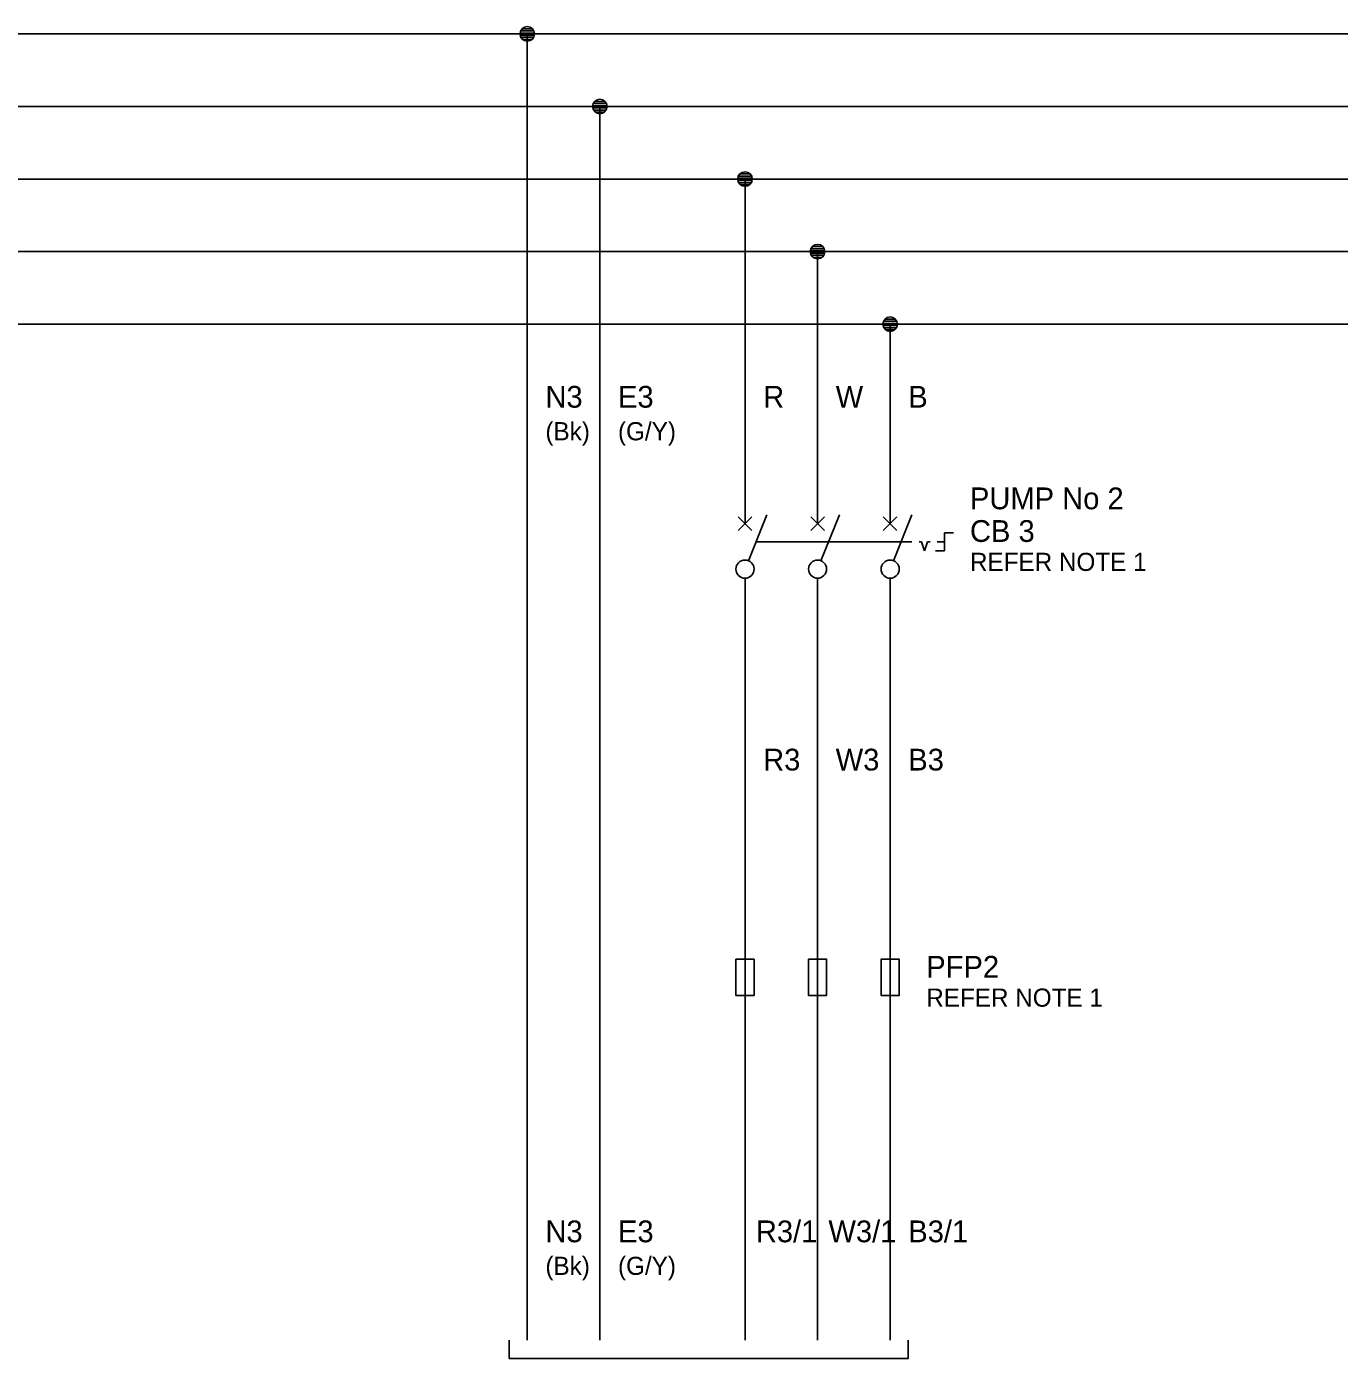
# Model space of a CAD drawing. Extents: x 0 to 841, y 0 to 594.
# Drawn here: x 491 to 671.9, y 147.5 to 331 of the extents above; entities that cross this region are included whole.
import ezdxf

# ---------------------------------------------------------------- set-up
doc = ezdxf.new("R2010")
doc.units = 0
doc.layers.add('Level 1', color=7, linetype='Continuous')
doc.layers.add('Level 10', color=7, linetype='Continuous')

msp = doc.modelspace()

# ---------------------------------------------------------------- linework, layer by layer
at = {"layer": 'Level 1'}
for p, q in [((50, 330), (800, 330)), ((560, 330), (560, 150)), ((50, 320), (800, 320)), ((570, 320), (570, 150)), ((800, 310), (50, 310)), ((590, 310), (590, 265)), ((50, 300), (800, 300)), ((600, 300), (600, 265)), ((50, 290), (800, 290)), ((610, 290), (610, 265)), ((590, 262.5), (590, 265)), ((600, 262.5), (600, 265)), ((610, 262.5), (610, 265)), ((589.06, 263.44), (590.94, 261.56)), ((590.94, 263.44), (589.06, 261.56)), ((590.46, 257.41), (593, 263.75)), ((599.06, 263.44), (600.94, 261.56)), ((600.94, 263.44), (599.06, 261.56)), ((600.46, 257.41), (603, 263.75)), ((609.06, 263.44), (610.94, 261.56)), ((610.94, 263.44), (609.06, 261.56)), ((610.46, 257.41), (613, 263.75)), ((591.5, 260), (611.5, 260)), ((590, 255), (590, 150)), ((600, 255), (600, 150)), ((610, 255), (610, 150))]:
    msp.add_line(p, q, dxfattribs=at)
msp.add_lwpolyline([(557.5, 150), (557.5, 147.5), (612.5, 147.5), (612.5, 150)], dxfattribs=at)
for centre in [(590, 256.25), (600, 256.25), (610, 256.25)]:
    msp.add_circle(centre, 1.25, dxfattribs=at)
at = {"layer": 'Level 10'}
for p, q in [((559.08, 330.4), (560.92, 330.4)), ((559.29, 330.7), (560.71, 330.7)), ((560, 331), (560, 331)), ((559.01, 330.1), (560.99, 330.1)), ((559.02, 329.8), (560.98, 329.8)), ((559.13, 329.5), (560.87, 329.5)), ((559.4, 329.2), (560.6, 329.2)), ((569.01, 320.1), (570.99, 320.1)), ((569.02, 319.8), (570.98, 319.8)), ((569.08, 320.4), (570.92, 320.4)), ((569.13, 319.5), (570.87, 319.5)), ((569.29, 320.7), (570.71, 320.7)), ((570, 321), (570, 321)), ((569.4, 319.2), (570.6, 319.2)), ((589.08, 310.4), (590.92, 310.4)), ((589.29, 310.7), (590.71, 310.7)), ((590, 311), (590, 311)), ((589.01, 310.1), (590.99, 310.1)), ((589.02, 309.8), (590.98, 309.8)), ((589.13, 309.5), (590.87, 309.5)), ((589.4, 309.2), (590.6, 309.2)), ((600, 301), (600, 301)), ((599.01, 300.1), (600.99, 300.1)), ((599.02, 299.8), (600.98, 299.8)), ((599.08, 300.4), (600.92, 300.4)), ((599.13, 299.5), (600.87, 299.5)), ((599.29, 300.7), (600.71, 300.7)), ((599.4, 299.2), (600.6, 299.2)), ((609.01, 290.1), (610.99, 290.1)), ((609.08, 290.4), (610.92, 290.4)), ((609.29, 290.7), (610.71, 290.7)), ((610, 291), (610, 291)), ((609.02, 289.8), (610.98, 289.8)), ((609.13, 289.5), (610.87, 289.5)), ((609.4, 289.2), (610.6, 289.2)), ((617.5, 258.75), (617.5, 261.25)), ((617.5, 261.25), (618.75, 261.25)), ((611.5, 260), (613, 260)), ((614, 260), (614.33, 260)), ((614.75, 258.75), (614.33, 260)), ((614.75, 258.75), (615.17, 260)), ((615.5, 260), (615.17, 260)), ((616.25, 258.75), (617.5, 258.75)), ((616.5, 260), (617.5, 260))]:
    msp.add_line(p, q, dxfattribs=at)
for points in [[(590, 197.5), (591.25, 197.5), (591.25, 202.5), (588.75, 202.5), (588.75, 197.5), (590, 197.5)], [(600, 197.5), (601.25, 197.5), (601.25, 202.5), (598.75, 202.5), (598.75, 197.5), (600, 197.5)], [(610, 197.5), (611.25, 197.5), (611.25, 202.5), (608.75, 202.5), (608.75, 197.5), (610, 197.5)]]:
    msp.add_lwpolyline(points, dxfattribs=at)
for centre in [(560, 330), (570, 320), (590, 310), (600, 300), (610, 290)]:
    msp.add_circle(centre, 1, dxfattribs=at)

# ---------------------------------------------------------------- texts
at = {"layer": 'Level 1'}
for s, height, p in [('N3', 3, (562.5, 278.5)), ('E3', 3, (572.5, 278.5)), ('R', 3, (592.5, 278.5)), ('W', 3, (602.5, 278.5)), ('B', 3, (612.5, 278.5)), ('(Bk)', 2.5, (562.5, 274)), ('(G/Y)', 2.5, (572.5, 274)), ('PUMP No 2', 3, (621, 264.5)), ('CB 3', 3, (621, 260)), ('REFER NOTE 1', 2.5, (621, 256)), ('R3', 3, (592.5, 228.5)), ('W3', 3, (602.5, 228.5)), ('B3', 3, (612.5, 228.5)), ('PFP2', 3, (614.98, 199.96)), ('REFER NOTE 1', 2.5, (614.98, 195.96)), ('N3', 3, (562.5, 163.5)), ('E3', 3, (572.5, 163.5)), ('R3/1', 3, (591.5, 163.5)), ('W3/1', 3, (601.5, 163.5)), ('B3/1', 3, (612.5, 163.5)), ('(Bk)', 2.5, (562.5, 159)), ('(G/Y)', 2.5, (572.5, 159))]:
    msp.add_text(s, height=height, dxfattribs=at).set_placement(p)

doc.saveas('drawing.dxf')
